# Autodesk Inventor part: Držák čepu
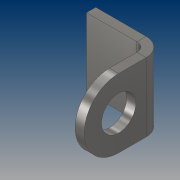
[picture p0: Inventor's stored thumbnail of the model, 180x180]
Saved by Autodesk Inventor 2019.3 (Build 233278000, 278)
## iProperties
Created: 2019-03
Part Number: Držák čepu
Material: Ocel, legovaná
Document SubType Name: Plech
Designer: B-hon
Density: 7.73 g/cm^3
Sheet Metal Rule: Výchozí_mm
Appearance: Pololeštěná
Author: B-hon
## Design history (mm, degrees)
node "Plocha1"
  sketch "Náčrt1"
    geometry: L1 (0, 0)-(30, 0); L2 (30, 0)-(30, 30); L3 (30, 30)-(0, 30); L4 (0, 30)-(0, 0)
    constraints: 8 end point, 2 parallel, 1 horizontal, 1 perpendicular
    dimensions: "d0" = 30 distance of L3.end L2.end; "d1" = 30 distance of L2.end L1.end
node "Obruba1"
fillet "Zaoblení1" dims "d13" = 15
sketch "Náčrt3"
  geometry: A1 r 15 centre (-12, 15) between (-12, 30) and (-12, 0) reference; 2 further points
  constraints: 1 coincident
hole "Díra1" sketch "Náčrt3" at (-12, 15) diameter "d14" = 15; stored, may be unused: countersink angle "d18" = 90 deg, drill point angle "d20" = 118 deg; dims "d15" = 6, "d16" = 4, "d17" = 2, "d19" = 4 (= Tloušťka)
node "Těleso1"
feature "Deska1" dims "d2" = 4 (= Tloušťka)
sketch "Náčrt2"
  geometry: L1 through (-15, 0) direction (1, 0); L2 through (0, 17.5) direction (0, 1); L3 (0, 35)-(-30, 35); L4 (-30, 35)-(-30, 0)
  constraints: 6 end point, 1 horizontal, 1 perpendicular, 1 vertical
feature "Deska2" dims "d2" = 4 (= Tloušťka), "d3" = 4 (= ŠířkaVýštipu), "d4" = 2 (= HloubkaVýštipu), "d5" = 8 (= MinimálníZbytek), "d6" = 4 (= PřechodovýPoloměr), "d7" = 35, "d8" = 90 deg, "d9" = 4 (= PoloměrOhybu), "d10" = 16 (= VelikostRohovéhoVýštipu), "d11" = 4 (= VelikostMezery), "d12" = 4 (= VelikostJacobihoPoloměru), "MezeraVystřižení" = 0.01
feature "Ohyb1" dims "d2" = 4 (= Tloušťka), "d3" = 4 (= ŠířkaVýštipu), "d4" = 2 (= HloubkaVýštipu), "d5" = 8 (= MinimálníZbytek), "d6" = 4 (= PřechodovýPoloměr), "d7" = 35, "d8" = 90 deg, "d9" = 4 (= PoloměrOhybu), "MezeraVystřižení" = 0.01
feature "Roh1" dims "d7" = 35, "d8" = 90 deg, "d10" = 16 (= VelikostRohovéhoVýštipu), "d11" = 4 (= VelikostMezery), "d12" = 4 (= VelikostJacobihoPoloměru)
other parameters: "Tloušťka" = 4 (derived), "KSoučinitel" = 4.4, "PoloměrOhybu" = 4 (= Tloušťka), "ŠířkaVýštipu" = 4 (= Tloušťka), "HloubkaVýštipu" = 2 (= 0.5 x Tloušťka), "VelikostRohovéhoVýštipu" = 16 (= 4 x Tloušťka), "MinimálníZbytek" = 8 (= 2 x Tloušťka), "PřechodovýPoloměr" = 4 (= PoloměrOhybu), "VelikostJacobihoPoloměru" = 4 (= PoloměrOhybu), "VelikostMezery" = 4 (= Tloušťka)
